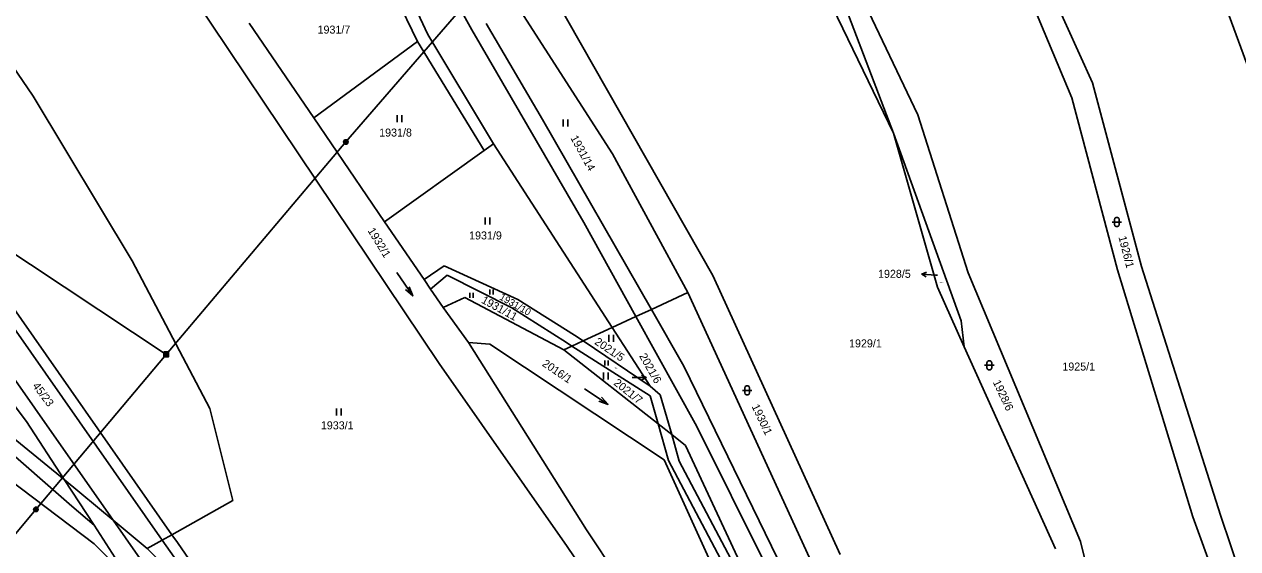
# Model space of a CAD drawing. Extents: x -609861 to -605046, y -1120287 to -1116307.
# Drawn here: x -607854.5 to -607596.7, y -1118047.5 to -1117936.1 of the extents above; entities that cross this region are included whole.
import ezdxf

# ---------------------------------------------------------------- set-up
doc = ezdxf.new("R2010")
doc.units = 0
for name, color, linetype in [('Vrstva 1', 7, 'Continuous'), ('Vrstva 2', 7, 'Continuous'), ('Vrstva 3', 7, 'Continuous'), ('Vrstva 4', 7, 'Continuous'), ('Vrstva 6', 7, 'Continuous'), ('Vrstva 7', 7, 'Continuous')]:
    doc.layers.add(name, color=color, linetype=linetype)

msp = doc.modelspace()

# ---------------------------------------------------------------- linework, layer by layer
at = {"layer": 'Vrstva 1'}
for p, q in [((-607852.62, -1117951.35), (-607906.94, -1117871.87)), ((-607766.33, -1118008.15), (-607851.47, -1117881.26)), ((-607782.59, -1117894.99), (-607759.41, -1117937.31)), ((-607627.5, -1117948.51), (-607648.04, -1117903.48)), ((-607651.2, -1117905.79), (-607631.91, -1117951.71)), ((-607781.87, -1117917.07), (-607770.93, -1117939.79)), ((-607664.63, -1117955.36), (-607680.92, -1117921.1)), ((-607683.96, -1117922.17), (-607669.82, -1117959.22)), ((-607708.21, -1117989.49), (-607744.53, -1117925.64)), ((-607669.82, -1117959.22), (-607686.73, -1117924.27)), ((-607601.62, -1117925.66), (-607581.02, -1117981.91)), ((-607773.24, -1117928.7), (-607768.71, -1117938.29)), ((-607729.51, -1117963.64), (-607751.38, -1117929.62)), ((-607792.97, -1117956.01), (-607806.71, -1117935.89)), ((-607744.37, -1117956.33), (-607756.36, -1117935.92)), ((-607768.71, -1117938.29), (-607754.76, -1117961.51)), ((-607759.41, -1117937.31), (-607735.59, -1117978.23)), ((-607792.97, -1117956.01), (-607770.93, -1117939.79)), ((-607770.93, -1117939.79), (-607756.74, -1117962.88)), ((-607617.09, -1117987.55), (-607627.5, -1117948.51)), ((-607831.58, -1117986.32), (-607852.62, -1117951.35)), ((-607631.91, -1117951.71), (-607622.23, -1117988.26)), ((-607777.93, -1117978.03), (-607792.97, -1117956.01)), ((-607721.24, -1117996.66), (-607744.37, -1117956.33)), ((-607653.95, -1117988.86), (-607664.63, -1117955.36)), ((-607669.82, -1117959.22), (-607655.41, -1117999.05)), ((-607660.46, -1117991.95), (-607669.82, -1117959.22)), ((-607754.76, -1117961.51), (-607756.74, -1117962.88)), ((-607754.76, -1117961.51), (-607729.55, -1118000.5)), ((-607756.74, -1117962.88), (-607777.93, -1117978.03)), ((-607713.49, -1117993.09), (-607729.51, -1117963.64)), ((-607854.04, -1118020.44), (-607895.4, -1117965.97)), ((-607917.93, -1117974.2), (-607846, -1118032.78)), ((-607872.32, -1117974.16), (-607823.12, -1118044.5)), ((-607769.52, -1117990.33), (-607777.93, -1117978.03)), ((-607735.59, -1117978.23), (-607724.52, -1117998.18)), ((-607815.06, -1118017.71), (-607831.58, -1117986.32)), ((-607769.52, -1117990.33), (-607765.28, -1117987.4)), ((-607765.28, -1117987.4), (-607749.61, -1117994.55)), ((-607600.35, -1118040.32), (-607617.09, -1117987.55)), ((-607768.15, -1117992.35), (-607769.52, -1117990.33)), ((-607768.15, -1117992.35), (-607764.63, -1117989.38)), ((-607764.63, -1117989.38), (-607750.89, -1117996.34)), ((-607681.1, -1118048.71), (-607708.21, -1117989.49)), ((-607630.06, -1118045.92), (-607653.95, -1117988.86)), ((-607622.23, -1117988.26), (-607606.16, -1118040.71)), ((-607765.46, -1117996.28), (-607768.15, -1117992.35)), ((-607713.49, -1117993.09), (-607721.24, -1117996.66)), ((-607686.87, -1118051.1), (-607713.49, -1117993.09)), ((-607654.76, -1118004.57), (-607660.46, -1117991.95)), ((-607760.85, -1117994.1), (-607765.46, -1117996.28)), ((-607739.85, -1118005.25), (-607760.85, -1117994.1)), ((-607749.61, -1117994.55), (-607737.59, -1118002.1)), ((-607765.46, -1117996.28), (-607760.1, -1118003.69)), ((-607750.89, -1117996.34), (-607739.3, -1118003.69)), ((-607724.52, -1117998.18), (-607729.55, -1118000.5)), ((-607721.24, -1117996.66), (-607724.52, -1117998.18)), ((-607724.52, -1117998.18), (-607711.55, -1118021.54)), ((-607714.32, -1118008.73), (-607721.24, -1117996.66)), ((-607729.55, -1118000.5), (-607735.73, -1118003.35)), ((-607729.55, -1118000.5), (-607721.51, -1118012.93)), ((-607655.41, -1117999.05), (-607654.76, -1118004.57)), ((-607735.73, -1118003.35), (-607738.11, -1118004.45)), ((-607737.59, -1118002.1), (-607735.73, -1118003.35)), ((-607735.73, -1118003.35), (-607721.51, -1118012.93)), ((-607760.1, -1118003.69), (-607735.05, -1118043.46)), ((-607760.1, -1118003.69), (-607755.56, -1118004.01)), ((-607755.56, -1118004.01), (-607718.55, -1118028.58)), ((-607738.11, -1118004.45), (-607739.85, -1118005.25)), ((-607739.85, -1118005.25), (-607719.8, -1118020.99)), ((-607739.3, -1118003.69), (-607738.11, -1118004.45)), ((-607738.11, -1118004.45), (-607721.49, -1118015.01)), ((-607635.38, -1118047.52), (-607654.76, -1118004.57)), ((-607739.13, -1118047.02), (-607766.33, -1118008.15)), ((-607694.34, -1118049.67), (-607714.32, -1118008.73)), ((-607721.51, -1118012.93), (-607719.34, -1118014.81)), ((-607721.49, -1118015.01), (-607719.8, -1118020.99)), ((-607719.34, -1118014.81), (-607716.92, -1118023.24)), ((-607810.15, -1118037.21), (-607815.06, -1118017.71)), ((-607846, -1118032.78), (-607854.04, -1118020.44)), ((-607719.8, -1118020.99), (-607717.61, -1118028.73)), ((-607719.8, -1118020.99), (-607716.92, -1118023.24)), ((-607711.55, -1118021.54), (-607696.95, -1118050.94)), ((-607844.36, -1118038.41), (-607861.61, -1118023.39)), ((-607716.92, -1118023.24), (-607715.31, -1118028.87)), ((-607716.92, -1118023.24), (-607714.01, -1118025.53)), ((-607714.01, -1118025.53), (-607693.02, -1118070.54)), ((-607864.8, -1118027.41), (-607839.64, -1118046.41)), ((-607718.55, -1118028.58), (-607699.22, -1118071.02)), ((-607701.36, -1118059.38), (-607717.61, -1118028.73)), ((-607715.31, -1118028.87), (-607699.52, -1118058.82)), ((-607846, -1118032.78), (-607835.63, -1118041.38)), ((-607839.67, -1118042.5), (-607846, -1118032.78)), ((-607839.67, -1118042.5), (-607844.36, -1118038.41)), ((-607823.12, -1118044.5), (-607810.15, -1118037.21)), ((-607835.63, -1118041.38), (-607828.35, -1118047.43)), ((-607606.16, -1118040.71), (-607580.43, -1118111.87)), ((-607576.61, -1118110.31), (-607600.35, -1118040.32)), ((-607832.58, -1118053.37), (-607839.67, -1118042.5)), ((-607825.16, -1118045.64), (-607823.12, -1118044.5)), ((-607823.12, -1118044.5), (-607821.94, -1118046.19)), ((-607735.05, -1118043.46), (-607716.18, -1118071.7)), ((-607839.64, -1118046.41), (-607832.58, -1118053.37)), ((-607828.35, -1118047.43), (-607825.16, -1118045.64)), ((-607813.77, -1118061.9), (-607828.35, -1118047.43)), ((-607821.94, -1118046.19), (-607804.52, -1118071.08)), ((-607720.71, -1118074.16), (-607739.13, -1118047.02)), ((-607616.72, -1118100.71), (-607630.06, -1118045.92))]:
    msp.add_line(p, q, dxfattribs=at)
at = {"layer": 'Vrstva 3'}
for p, q in [((-607775.24, -1117955.43), (-607775.24, -1117956.93)), ((-607774.24, -1117956.93), (-607774.24, -1117955.43)), ((-607739.98, -1117956.3), (-607739.98, -1117957.8)), ((-607738.98, -1117957.8), (-607738.98, -1117956.3)), ((-607756.57, -1117977.12), (-607756.57, -1117978.62)), ((-607755.57, -1117978.62), (-607755.57, -1117977.12)), ((-607775.343, -1117988.843), (-607771.957, -1117993.797)), ((-607759.83, -1117993.15), (-607759.83, -1117994.2)), ((-607759.13, -1117994.2), (-607759.13, -1117993.15)), ((-607755.55, -1117992.42), (-607755.55, -1117993.47)), ((-607754.85, -1117993.47), (-607754.85, -1117992.42)), ((-607730.3, -1118002.05), (-607730.3, -1118003.55)), ((-607729.3, -1118003.55), (-607729.3, -1118002.05)), ((-607731.13, -1118007.5), (-607731.13, -1118008.55)), ((-607730.43, -1118008.55), (-607730.43, -1118007.5)), ((-607731.4, -1118010.05), (-607731.4, -1118011.55)), ((-607730.4, -1118011.55), (-607730.4, -1118010.05)), ((-607735.429, -1118013.52), (-607730.431, -1118016.84)), ((-607788.14, -1118017.7), (-607788.14, -1118019.2)), ((-607787.14, -1118019.2), (-607787.14, -1118017.7))]:
    msp.add_line(p, q, dxfattribs=at)
for points in [[(-607622.85, -1117977.6), (-607622.75, -1117977.31), (-607622.5, -1117977.13), (-607622.19, -1117977.13), (-607621.94, -1117977.31), (-607621.84, -1117977.6), (-607621.84, -1117978.6), (-607621.94, -1117978.89), (-607622.19, -1117979.07), (-607622.5, -1117979.07), (-607622.75, -1117978.89), (-607622.85, -1117978.6)], [(-607649.93, -1118008.03), (-607649.83, -1118007.74), (-607649.58, -1118007.56), (-607649.27, -1118007.56), (-607649.02, -1118007.74), (-607648.92, -1118008.03), (-607648.92, -1118009.03), (-607649.02, -1118009.32), (-607649.27, -1118009.5), (-607649.58, -1118009.5), (-607649.83, -1118009.32), (-607649.93, -1118009.03)], [(-607701.38, -1118013.35), (-607701.28, -1118013.06), (-607701.03, -1118012.88), (-607700.72, -1118012.88), (-607700.47, -1118013.06), (-607700.37, -1118013.35), (-607700.37, -1118014.35), (-607700.47, -1118014.64), (-607700.72, -1118014.82), (-607701.03, -1118014.82), (-607701.28, -1118014.64), (-607701.38, -1118014.35)]]:
    msp.add_lwpolyline(points, close=True, dxfattribs=at)
for points in [[(-607623.35, -1117978.1), (-607622.08, -1117978.1), (-607621.35, -1117978.1)], [(-607772.673, -1117991.863), (-607771.957, -1117993.797), (-607773.498, -1117992.428)], [(-607650.43, -1118008.53), (-607649.16, -1118008.53), (-607648.43, -1118008.53)], [(-607701.88, -1118013.85), (-607700.61, -1118013.85), (-607699.88, -1118013.85)], [(-607731.82, -1118015.317), (-607730.431, -1118016.84), (-607732.374, -1118016.15)]]:
    msp.add_lwpolyline(points, dxfattribs=at)
at = {"layer": 'Vrstva 4'}
for p, q in [((-607901.32, -1117936.93), (-607825.16, -1118045.64)), ((-607835.63, -1118041.38), (-607903.44, -1117944.59)), ((-607820.03, -1118063.65), (-607835.63, -1118041.38)), ((-607825.16, -1118045.64), (-607813.77, -1118061.9))]:
    msp.add_line(p, q, dxfattribs=at)
at = {"layer": 'Vrstva 6'}
for p, q in [((-607752.73, -1117922.44), (-607786.16, -1117961.1)), ((-607786.16, -1117961.1), (-607824.31, -1118006.2)), ((-607824.31, -1118006.2), (-607871.11, -1117975.24)), ((-607824.31, -1118006.2), (-607852.01, -1118039.13)), ((-607852.01, -1118039.13), (-607882.12, -1118074.83))]:
    msp.add_line(p, q, dxfattribs=at)
for points in [[(-607786.31, -1117960.62), (-607786, -1117960.62), (-607785.75, -1117960.8), (-607785.65, -1117961.09), (-607785.75, -1117961.38), (-607786, -1117961.56), (-607786.31, -1117961.56), (-607786.56, -1117961.38), (-607786.66, -1117961.09), (-607786.56, -1117960.8), (-607786.31, -1117960.62), (-607786.28, -1117960.66), (-607786.04, -1117960.66), (-607785.88, -1117960.74), (-607786.44, -1117960.74), (-607786.52, -1117960.82), (-607785.8, -1117960.82), (-607785.8, -1117960.9), (-607786.52, -1117960.9), (-607786.56, -1117960.98), (-607785.76, -1117960.98), (-607785.72, -1117961.06), (-607786.6, -1117961.06), (-607786.6, -1117961.14), (-607785.72, -1117961.14), (-607785.75, -1117961.22), (-607786.56, -1117961.22), (-607786.55, -1117961.3), (-607785.74, -1117961.3), (-607785.79, -1117961.38), (-607786.51, -1117961.38), (-607786.43, -1117961.46), (-607785.87, -1117961.46), (-607785.98, -1117961.54), (-607786.32, -1117961.54)], [(-607824.81, -1118005.7), (-607823.81, -1118005.7), (-607823.81, -1118006.7), (-607824.81, -1118006.7), (-607824.81, -1118005.7), (-607824.75, -1118005.76), (-607823.87, -1118005.76), (-607823.87, -1118005.84), (-607824.75, -1118005.84), (-607824.75, -1118005.92), (-607823.87, -1118005.92), (-607823.87, -1118006), (-607824.75, -1118006), (-607824.75, -1118006.08), (-607823.87, -1118006.08), (-607823.87, -1118006.16), (-607824.75, -1118006.16), (-607824.75, -1118006.24), (-607823.87, -1118006.24), (-607823.87, -1118006.32), (-607824.75, -1118006.32), (-607824.75, -1118006.4), (-607823.87, -1118006.4), (-607823.87, -1118006.48), (-607824.75, -1118006.48), (-607824.75, -1118006.56), (-607823.87, -1118006.56), (-607823.87, -1118006.64), (-607824.75, -1118006.64)], [(-607852.16, -1118038.65), (-607851.85, -1118038.65), (-607851.6, -1118038.83), (-607851.5, -1118039.12), (-607851.6, -1118039.41), (-607851.85, -1118039.59), (-607852.16, -1118039.59), (-607852.41, -1118039.41), (-607852.51, -1118039.12), (-607852.41, -1118038.83), (-607852.16, -1118038.65), (-607852.13, -1118038.69), (-607851.89, -1118038.69), (-607851.73, -1118038.77), (-607852.29, -1118038.77), (-607852.37, -1118038.85), (-607851.65, -1118038.85), (-607851.65, -1118038.93), (-607852.37, -1118038.93), (-607852.41, -1118039.01), (-607851.61, -1118039.01), (-607851.57, -1118039.09), (-607852.45, -1118039.09), (-607852.45, -1118039.17), (-607851.57, -1118039.17), (-607851.6, -1118039.25), (-607852.41, -1118039.25), (-607852.4, -1118039.33), (-607851.59, -1118039.33), (-607851.64, -1118039.41), (-607852.36, -1118039.41), (-607852.28, -1118039.49), (-607851.72, -1118039.49), (-607851.83, -1118039.57), (-607852.17, -1118039.57)]]:
    msp.add_lwpolyline(points, dxfattribs=at)
at = {"layer": 'Vrstva 7'}
for p, q in [((-607663.803, -1117989.164), (-607660.81, -1117989.37)), ((-607660.43, -1117989.4), (-607660.81, -1117989.37)), ((-607722.34, -1118011.151), (-607725.34, -1118011.15))]:
    msp.add_line(p, q, dxfattribs=at)
for points in [[(-607662.84, -1117989.731), (-607663.803, -1117989.164), (-607662.771, -1117988.734)], [(-607723.34, -1118010.651), (-607722.34, -1118011.151), (-607723.34, -1118011.651)]]:
    msp.add_lwpolyline(points, dxfattribs=at)

# ---------------------------------------------------------------- texts
at = {"layer": 'Vrstva 2'}
for s, height, p in [('1931/7', 1.7, (-607792.167, -1117938.09)), ('1931/8', 1.7, (-607779.077, -1117959.95)), ('1931/9', 1.7, (-607759.967, -1117981.8)), ('1928/5', 0.2, (-607660.004, -1117991.02)), ('1929/1', 1.7, (-607679.237, -1118004.72)), ('1925/1', 1.7, (-607633.917, -1118009.64)), ('2021/6', 0.2, (-607729.132, -1118009.23)), ('1933/1', 1.7, (-607791.467, -1118022.13))]:
    msp.add_text(s, height=height, dxfattribs=at).set_placement(p)
for s, height, rotation, p in [('1931/14', 1.7, 298.79749, (-607738.491, -1117960.244)), ('1932/1', 1.7, 301.49039, (-607781.595, -1117979.935)), ('1926/1', 1.7, 284.41625, (-607622.012, -1117981.29)), ('1931/11', 1.7, 331.2269, (-607757.506, -1117995.169)), ('1931/10', 1.5, 330.31017, (-607753.669, -1117994.472)), ('2021/5', 1.7, 325.7838, (-607733.454, -1118003.903)), ('2016/1', 1.7, 325.7838, (-607744.584, -1118008.533)), ('45/23', 1.7, 306.87619, (-607852.838, -1118012.93)), ('2021/7', 1.7, 321.31473, (-607729.395, -1118012.528)), ('1928/6', 1.7, 295.18786, (-607648.723, -1118012.095)), ('1930/1', 1.7, 295.18786, (-607699.973, -1118017.245))]:
    msp.add_text(s, height=height, rotation=rotation, dxfattribs=at).set_placement(p)
at = {"layer": 'Vrstva 7'}
msp.add_text('1928/5', height=1.7, dxfattribs=at).set_placement((-607673.081, -1117989.95))
msp.add_text('2021/6', height=1.7, rotation=299.71422, dxfattribs=at).set_placement((-607723.891, -1118006.548))

doc.saveas('drawing.dxf')
